// Mitsubishi GX Works2 project: MC-30MR-6MT-430-FX-B例程   PLC: FX1S

PROGRAM MAIN
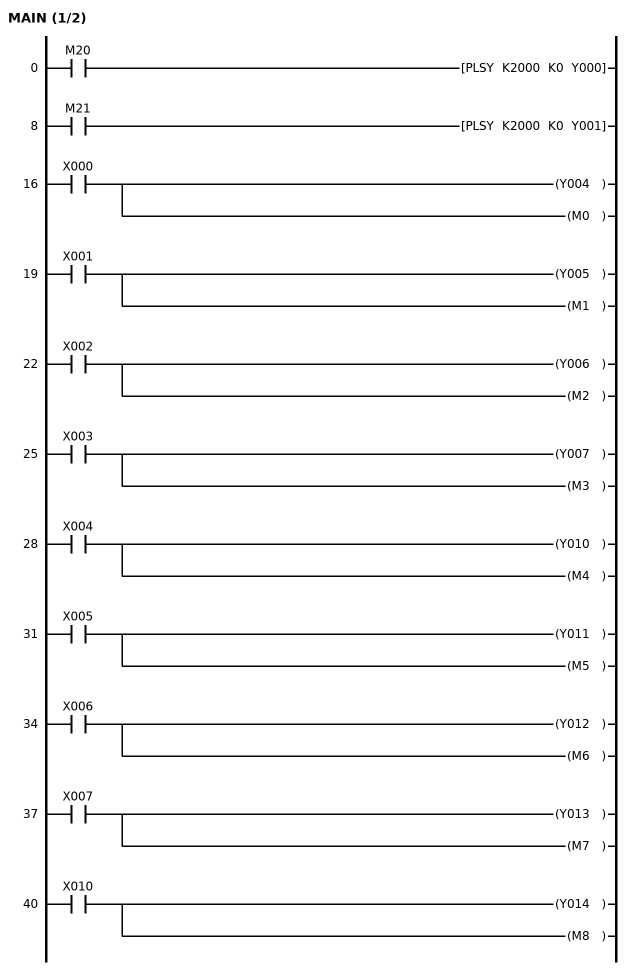
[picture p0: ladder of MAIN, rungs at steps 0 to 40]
0     LD      M20
      PLSY    K2000 K0 Y000
8     LD      M21
      PLSY    K2000 K0 Y001
16    LD      X000
      OUT     Y004
      OUT     M0
19    LD      X001
      OUT     Y005
      OUT     M1
22    LD      X002
      OUT     Y006
      OUT     M2
25    LD      X003
      OUT     Y007
      OUT     M3
28    LD      X004
      OUT     Y010
      OUT     M4
31    LD      X005
      OUT     Y011
      OUT     M5
34    LD      X006
      OUT     Y012
      OUT     M6
37    LD      X007
      OUT     Y013
      OUT     M7
40    LD      X010
      OUT     Y014
      OUT     M8
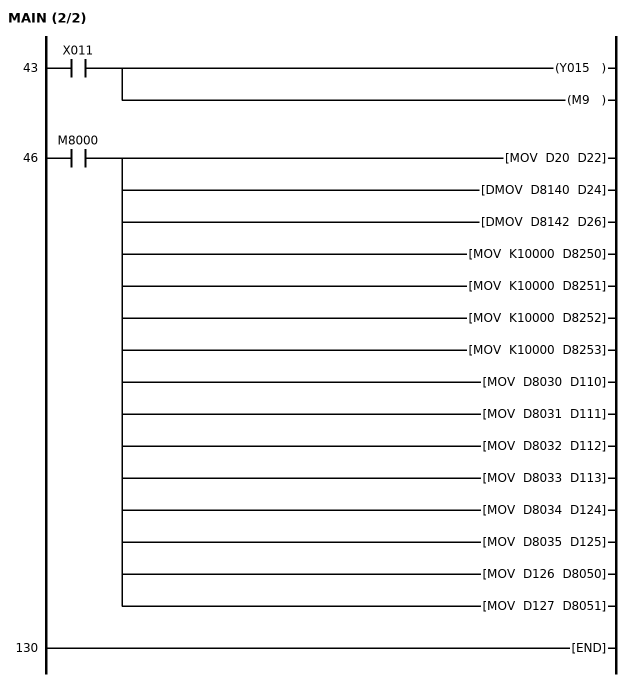
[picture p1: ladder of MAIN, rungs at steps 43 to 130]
43    LD      X011
      OUT     Y015
      OUT     M9
46    LD      M8000
      MOV     D20 D22
      DMOV    D8140 D24
      DMOV    D8142 D26
      MOV     K10000 D8250
      MOV     K10000 D8251
      MOV     K10000 D8252
      MOV     K10000 D8253
      MOV     D8030 D110
      MOV     D8031 D111
      MOV     D8032 D112
      MOV     D8033 D113
      MOV     D8034 D124
      MOV     D8035 D125
      MOV     D126 D8050
      MOV     D127 D8051
130   END
END_PROGRAM
